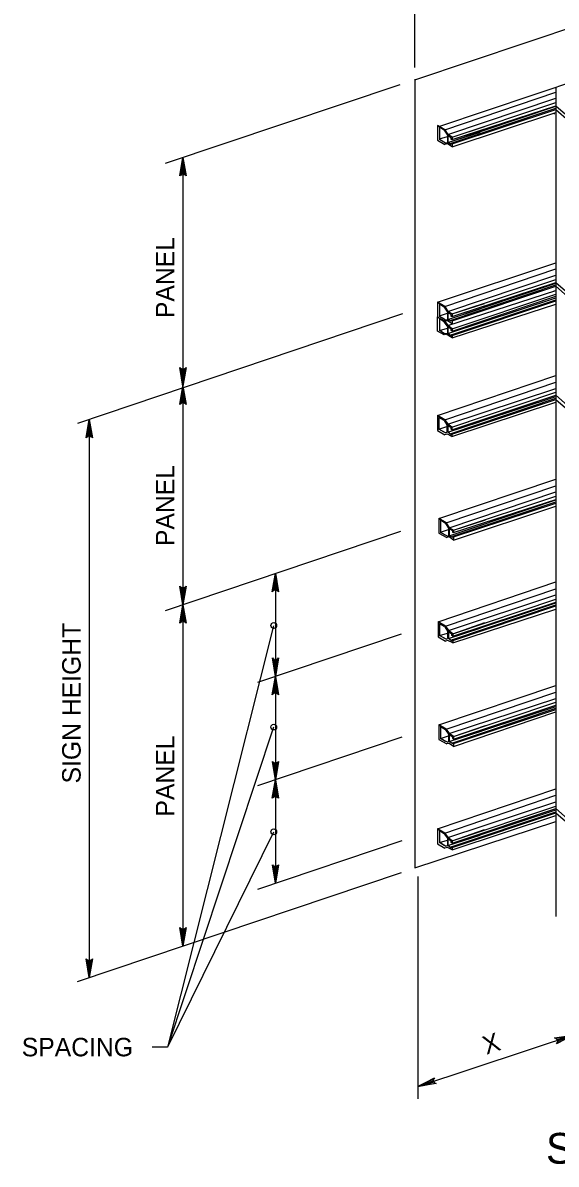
# Model space of a CAD drawing. Extents: x 650495 to 652241, y 298458 to 299646.
# Drawn here: x 650741.8 to 650828.3, y 299357.5 to 299542.7 of the extents above; entities that cross this region are included whole.
import ezdxf

# ---------------------------------------------------------------- set-up
doc = ezdxf.new("R2010")
doc.units = 0
doc.layers.add('2', color=7, linetype='Continuous')
doc.layers.add('3', color=7, linetype='Continuous')

# ---------------------------------------------------------------- blocks, each defined once
blk = doc.blocks.new('RARROW')
at = {"layer": '3'}
blk.add_lwpolyline([(-2.2695, 0.285), (-2.184875, 0.12075), (0, 0), (-2.2695, 0.285), (-2.38575, 0.384625), (0, 0), (-2.183125, -0.108), (-2.262875, -0.2705), (0, 0), (-2.38575, -0.379125), (-2.262875, -0.2705)], dxfattribs=at)

msp = doc.modelspace()

# ---------------------------------------------------------------- linework, layer by layer
at = {"layer": '2'}
for p, q in [((650805.4, 299533.47), (650908.3, 299568.07)), ((650805.4, 299535.47), (650805.4, 299567.07)), ((650809.3, 299525.87), (650904, 299557.67)), ((650803, 299532.67), (650764.9, 299519.87)), ((650805.4, 299533.57), (650805.4, 299405.57)), ((650828.3, 299532.27), (650828.3, 299397.67)), ((650810.3, 299525.37), (650828.3, 299531.47)), ((650810.8, 299524.57), (650828.3, 299530.47)), ((650810.8, 299523.27), (650828.3, 299529.17)), ((650811.3, 299523.17), (650828.3, 299528.87)), ((650811.5, 299524.17), (650828.3, 299529.77)), ((650811.5, 299523.77), (650828.3, 299529.27)), ((650811.5, 299523.07), (650828.3, 299528.67)), ((650828.3, 299529.27), (650832.8, 299525.37)), ((650828.3, 299528.67), (650832.8, 299524.67)), ((650811.5, 299522.57), (650828.3, 299528.17)), ((650828, 299527.97), (650828, 299527.87)), ((650828.3, 299528.17), (650828.3, 299528.17)), ((650809.1, 299526.07), (650809.1, 299526.07)), ((650810.3, 299525.37), (650809.1, 299526.07)), ((650809.1, 299526.07), (650809.1, 299523.67)), ((650809.1, 299526.07), (650810.3, 299525.37)), ((650809.4, 299525.77), (650809.4, 299523.77)), ((650810.2, 299525.27), (650809.4, 299525.77)), ((650810.2, 299525.27), (650810.7, 299524.47)), ((650810.3, 299525.37), (650810.8, 299524.57)), ((650810.8, 299523.27), (650816, 299524.97)), ((650811.5, 299524.17), (650816.7, 299525.87)), ((650811.5, 299523.77), (650816.7, 299525.47)), ((650809.1, 299523.67), (650810.3, 299522.97)), ((650809.4, 299523.87), (650810.7, 299524.27)), ((650810.4, 299523.17), (650809.4, 299523.77)), ((650810.2, 299523.37), (650809.4, 299523.77)), ((650810.7, 299523.07), (650810.3, 299522.97)), ((650810.4, 299523.17), (650810.7, 299523.27)), ((650810.7, 299524.57), (650810.7, 299523.27)), ((650811.5, 299522.57), (650810.7, 299523.07)), ((650811.5, 299524.17), (650810.8, 299524.57)), ((650811.3, 299524.07), (650810.8, 299524.37)), ((650811.3, 299524.07), (650810.8, 299524.37)), ((650810.8, 299524.37), (650810.8, 299523.27)), ((650811.3, 299522.97), (650810.8, 299523.27)), ((650811.3, 299524.07), (650811.3, 299523.87)), ((650811.3, 299523.77), (650811.3, 299524.07)), ((650811.5, 299523.77), (650811.3, 299523.87)), ((650811.5, 299523.77), (650811.3, 299523.77)), ((650811.3, 299523.17), (650811.3, 299522.97)), ((650811.5, 299523.07), (650811.3, 299523.17)), ((650811.3, 299523.17), (650811.3, 299522.97)), ((650811.5, 299523.07), (650811.3, 299523.17)), ((650811.5, 299524.17), (650811.5, 299523.77)), ((650811.5, 299524.17), (650811.5, 299523.77)), ((650811.5, 299523.07), (650811.5, 299522.57)), ((650811.5, 299523.07), (650811.5, 299522.57)), ((650767.8, 299520.87), (650767.8, 299512.47)), ((650767.8, 299520.87), (650767.8, 299483.77)), ((650809.1, 299497.37), (650828.3, 299503.77)), ((650810.3, 299496.67), (650828.3, 299502.77)), ((650810.8, 299495.87), (650828.3, 299501.77)), ((650811.5, 299495.47), (650828.3, 299501.07)), ((650810.8, 299494.57), (650828.3, 299500.47)), ((650810.8, 299493.57), (650828.3, 299499.27)), ((650811.3, 299494.47), (650828.3, 299500.17)), ((650811.5, 299495.07), (650828.3, 299500.57)), ((650811.5, 299494.37), (650828.3, 299499.97)), ((650828, 299499.27), (650828, 299499.17)), ((650828.3, 299500.57), (650832.8, 299496.67)), ((650828.3, 299499.97), (650832.8, 299495.97)), ((650828.3, 299499.47), (650828.3, 299499.47)), ((650810.3, 299496.67), (650809.1, 299497.37)), ((650809.1, 299497.37), (650809.1, 299494.97)), ((650809.1, 299497.37), (650810.3, 299496.67)), ((650809.4, 299497.07), (650809.4, 299495.07)), ((650810.2, 299496.57), (650809.4, 299497.07)), ((650810.8, 299492.27), (650828.3, 299498.07)), ((650811.3, 299492.07), (650828.3, 299497.77)), ((650811.5, 299493.07), (650828.3, 299498.67)), ((650811.5, 299492.67), (650828.3, 299498.37)), ((650811.5, 299491.97), (650828.3, 299497.57)), ((650811.5, 299495.47), (650816.7, 299497.17)), ((650811.5, 299491.57), (650828.3, 299497.07)), ((650803.4, 299495.47), (650750.69, 299477.67)), ((650809.4, 299495.17), (650810.7, 299495.57)), ((650810.2, 299496.57), (650810.7, 299495.77)), ((650810.3, 299496.67), (650810.8, 299495.87)), ((650810.7, 299495.87), (650810.7, 299494.57)), ((650810.8, 299494.57), (650816, 299496.27)), ((650811.5, 299495.47), (650810.8, 299495.87)), ((650811.3, 299495.37), (650810.8, 299495.67)), ((650811.3, 299495.37), (650810.8, 299495.67)), ((650810.8, 299495.67), (650810.8, 299494.57)), ((650811.3, 299495.37), (650811.3, 299495.17)), ((650811.3, 299495.07), (650811.3, 299495.37)), ((650811.5, 299495.07), (650811.3, 299495.17)), ((650811.5, 299495.07), (650816.7, 299496.77)), ((650811.5, 299495.47), (650811.5, 299495.07)), ((650811.5, 299495.47), (650811.5, 299495.07)), ((650809.1, 299492.67), (650809.1, 299494.97)), ((650809.1, 299494.97), (650810.3, 299494.27)), ((650810.4, 299494.47), (650809.4, 299495.07)), ((650810.2, 299494.67), (650809.4, 299495.07)), ((650809.4, 299494.67), (650809.4, 299492.77)), ((650810.2, 299494.17), (650809.4, 299494.67)), ((650810.7, 299493.47), (650810.2, 299494.17)), ((650810.7, 299494.37), (650810.3, 299494.27)), ((650810.3, 299494.27), (650810.8, 299493.57)), ((650810.4, 299494.47), (650810.7, 299494.57)), ((650810.5, 299493.87), (650810.5, 299493.87)), ((650811.5, 299493.87), (650810.7, 299494.37)), ((650810.7, 299493.47), (650810.7, 299492.37)), ((650811.3, 299494.27), (650810.8, 299494.57)), ((650811.5, 299493.07), (650810.8, 299493.57)), ((650811.3, 299492.97), (650810.8, 299493.37)), ((650810.8, 299493.37), (650810.8, 299492.27)), ((650811.5, 299495.07), (650811.3, 299495.07)), ((650811.3, 299494.47), (650811.3, 299494.27)), ((650811.5, 299494.37), (650811.3, 299494.47)), ((650811.3, 299494.47), (650811.3, 299494.27)), ((650811.5, 299494.37), (650811.3, 299494.47)), ((650811.5, 299494.37), (650811.5, 299493.87)), ((650811.5, 299494.37), (650811.5, 299493.87)), ((650810.2, 299492.07), (650809.1, 299492.67)), ((650809.4, 299492.77), (650810.7, 299493.17)), ((650810.2, 299492.27), (650809.4, 299492.77)), ((650810.2, 299492.27), (650810.7, 299492.37)), ((650810.5, 299492.17), (650810.2, 299492.07)), ((650811.5, 299491.57), (650810.5, 299492.17)), ((650811.3, 299491.87), (650810.8, 299492.27)), ((650811.3, 299492.77), (650811.3, 299492.97)), ((650811.5, 299492.67), (650811.3, 299492.77)), ((650811.3, 299492.07), (650811.3, 299491.87)), ((650811.5, 299491.97), (650811.3, 299492.07)), ((650811.5, 299493.07), (650811.5, 299492.67)), ((650811.5, 299491.97), (650811.5, 299491.57)), ((650809.1, 299478.97), (650828.3, 299485.47)), ((650810.3, 299478.27), (650828.3, 299484.37)), ((650767.8, 299483.77), (650767.8, 299437.57)), ((650810.8, 299477.57), (650828.3, 299483.37)), ((650811.4, 299477.07), (650828.3, 299482.77)), ((650811.4, 299476.67), (650828.3, 299482.27)), ((650828.3, 299482.27), (650832.8, 299478.27)), ((650810.8, 299476.27), (650828.3, 299482.07)), ((650811.3, 299476.07), (650828.3, 299481.77)), ((650811.4, 299475.97), (650828.3, 299481.57)), ((650811.4, 299475.57), (650828.3, 299481.17)), ((650828.3, 299481.57), (650832.8, 299477.67)), ((650809.1, 299478.97), (650809.1, 299478.97)), ((650810.3, 299478.27), (650809.1, 299478.97)), ((650809.1, 299478.97), (650809.1, 299476.57)), ((650809.1, 299478.97), (650810.3, 299478.27)), ((650809.3, 299478.67), (650809.3, 299476.77)), ((650810.2, 299478.17), (650809.3, 299478.67)), ((650811.4, 299477.07), (650816.7, 299478.87)), ((650752.6, 299478.31), (650752.6, 299387.77)), ((650809.1, 299476.57), (650810.3, 299475.87)), ((650809.3, 299476.77), (650810.6, 299477.17)), ((650810.4, 299476.17), (650809.3, 299476.77)), ((650810.2, 299476.27), (650809.3, 299476.77)), ((650810.2, 299478.17), (650810.6, 299477.47)), ((650810.3, 299478.27), (650810.8, 299477.57)), ((650810.6, 299477.47), (650810.6, 299476.27)), ((650810.8, 299476.27), (650815.9, 299477.97)), ((650811.4, 299477.07), (650810.8, 299477.57)), ((650811.3, 299476.97), (650810.8, 299477.37)), ((650811.3, 299476.97), (650810.8, 299477.37)), ((650810.8, 299477.37), (650810.8, 299476.27)), ((650811.3, 299476.97), (650811.3, 299476.77)), ((650811.3, 299476.77), (650811.3, 299476.97)), ((650811.4, 299476.67), (650811.3, 299476.77)), ((650811.4, 299476.67), (650811.3, 299476.77)), ((650811.4, 299476.67), (650816.7, 299478.37)), ((650811.4, 299477.07), (650811.4, 299476.67)), ((650811.4, 299477.07), (650811.4, 299476.67)), ((650810.7, 299475.97), (650810.3, 299475.87)), ((650810.4, 299476.17), (650810.6, 299476.27)), ((650811.4, 299475.57), (650810.7, 299475.97)), ((650811.3, 299475.87), (650810.8, 299476.27)), ((650811.3, 299476.07), (650811.3, 299475.87)), ((650811.4, 299475.97), (650811.3, 299476.07)), ((650811.3, 299476.07), (650811.3, 299475.87)), ((650811.4, 299475.97), (650811.3, 299476.07)), ((650811.4, 299475.97), (650811.4, 299475.57)), ((650811.4, 299475.97), (650811.4, 299475.57)), ((650809.3, 299462.27), (650828.3, 299468.67)), ((650810.5, 299461.57), (650828.3, 299467.57)), ((650811, 299460.77), (650828.3, 299466.57)), ((650811.7, 299460.37), (650828.3, 299465.87)), ((650811, 299459.47), (650828.3, 299465.27)), ((650811.6, 299459.37), (650828.3, 299464.97)), ((650811.7, 299459.97), (650828.3, 299465.37)), ((650811.7, 299459.27), (650828.3, 299464.77)), ((650811.7, 299458.77), (650828.3, 299464.27)), ((650809.3, 299462.27), (650809.3, 299462.27)), ((650810.5, 299461.57), (650809.3, 299462.27)), ((650809.3, 299462.27), (650809.3, 299459.87)), ((650809.3, 299462.27), (650810.5, 299461.57)), ((650809.6, 299461.97), (650809.6, 299459.97)), ((650810.4, 299461.47), (650809.6, 299461.97)), ((650811.7, 299460.37), (650816.9, 299462.07)), ((650803.1, 299460.17), (650764.9, 299447.27)), ((650809.6, 299460.07), (650810.9, 299460.47)), ((650810.7, 299459.37), (650809.6, 299459.97)), ((650810.4, 299459.57), (650809.6, 299459.97)), ((650810.4, 299461.47), (650810.9, 299460.67)), ((650810.5, 299461.57), (650811, 299460.77)), ((650810.9, 299460.77), (650810.9, 299459.47)), ((650811, 299459.47), (650816.2, 299461.17)), ((650811.7, 299460.37), (650811, 299460.77)), ((650811.6, 299460.27), (650811, 299460.57)), ((650811.6, 299460.27), (650811, 299460.57)), ((650811, 299460.57), (650811, 299459.47)), ((650811.6, 299460.27), (650811.6, 299460.07)), ((650811.6, 299459.97), (650811.6, 299460.27)), ((650811.7, 299459.97), (650811.6, 299460.07)), ((650811.7, 299459.97), (650811.6, 299459.97)), ((650811.7, 299459.97), (650816.9, 299461.67)), ((650811.7, 299460.37), (650811.7, 299459.97)), ((650811.7, 299460.37), (650811.7, 299459.97)), ((650809.3, 299459.87), (650810.6, 299459.17)), ((650811, 299459.27), (650810.6, 299459.17)), ((650810.7, 299459.37), (650810.9, 299459.47)), ((650811.6, 299459.17), (650811, 299459.47)), ((650811.7, 299458.77), (650811, 299459.27)), ((650811.6, 299459.37), (650811.6, 299459.17)), ((650811.7, 299459.27), (650811.6, 299459.37)), ((650811.6, 299459.37), (650811.6, 299459.17)), ((650811.7, 299459.27), (650811.6, 299459.37)), ((650811.7, 299459.27), (650811.7, 299458.77)), ((650811.7, 299459.27), (650811.7, 299458.77)), ((650782.8, 299453.31), (650782.8, 299403.07)), ((650809.2, 299445.47), (650828.3, 299451.97)), ((650810.4, 299444.77), (650828.3, 299450.87)), ((650810.9, 299444.07), (650828.3, 299449.87)), ((650811.6, 299443.57), (650828.3, 299449.17)), ((650767.8, 299448.27), (650767.8, 299392.87)), ((650810.9, 299442.77), (650828.3, 299448.57)), ((650811.4, 299442.57), (650828.3, 299448.27)), ((650811.6, 299443.17), (650828.3, 299448.67)), ((650811.6, 299442.47), (650828.3, 299448.07)), ((650811.6, 299442.07), (650828.3, 299447.57)), ((650809.2, 299445.47), (650809.2, 299445.47)), ((650810.4, 299444.77), (650809.2, 299445.47)), ((650809.2, 299445.47), (650809.2, 299443.07)), ((650809.2, 299445.47), (650810.4, 299444.77)), ((650809.4, 299445.17), (650809.4, 299443.27)), ((650810.3, 299444.67), (650809.4, 299445.17)), ((650811.6, 299443.57), (650816.8, 299445.37)), ((650782.5, 299444.87), (650765.3, 299376.47)), ((650803.2, 299443.47), (650779.9, 299435.67)), ((650809.4, 299443.27), (650810.7, 299443.67)), ((650810.5, 299442.67), (650809.4, 299443.27)), ((650810.3, 299442.77), (650809.4, 299443.27)), ((650810.3, 299444.67), (650810.7, 299443.97)), ((650810.4, 299444.77), (650810.9, 299444.07)), ((650810.7, 299443.97), (650810.7, 299442.77)), ((650810.9, 299442.77), (650816, 299444.47)), ((650811.6, 299443.57), (650810.9, 299444.07)), ((650811.4, 299443.47), (650810.9, 299443.87)), ((650811.4, 299443.47), (650810.9, 299443.87)), ((650810.9, 299443.87), (650810.9, 299442.77)), ((650811.4, 299443.47), (650811.4, 299443.27)), ((650811.4, 299443.27), (650811.4, 299443.47)), ((650811.6, 299443.17), (650811.4, 299443.27)), ((650811.6, 299443.17), (650811.4, 299443.27)), ((650811.6, 299443.17), (650816.8, 299444.87)), ((650811.6, 299443.57), (650811.6, 299443.17)), ((650811.6, 299443.57), (650811.6, 299443.17)), ((650809.2, 299443.07), (650810.4, 299442.37)), ((650810.8, 299442.47), (650810.4, 299442.37)), ((650810.5, 299442.67), (650810.7, 299442.77)), ((650811.6, 299442.07), (650810.8, 299442.47)), ((650811.4, 299442.37), (650810.9, 299442.77)), ((650811.4, 299442.57), (650811.4, 299442.37)), ((650811.6, 299442.47), (650811.4, 299442.57)), ((650811.4, 299442.57), (650811.4, 299442.37)), ((650811.6, 299442.47), (650811.4, 299442.57)), ((650811.6, 299442.47), (650811.6, 299442.07)), ((650811.6, 299442.47), (650811.6, 299442.07)), ((650809.3, 299428.77), (650828.3, 299435.17)), ((650810.5, 299428.07), (650828.3, 299434.07)), ((650811, 299427.37), (650828.3, 299433.07)), ((650811.7, 299426.87), (650828.3, 299432.47)), ((650811, 299426.07), (650828.3, 299431.77)), ((650811.6, 299425.87), (650828.3, 299431.47)), ((650811.7, 299426.47), (650828.3, 299431.97)), ((650811.7, 299425.77), (650828.3, 299431.27)), ((650811.7, 299425.27), (650828.3, 299430.87)), ((650809.3, 299428.77), (650809.3, 299428.77)), ((650810.5, 299428.07), (650809.3, 299428.77)), ((650809.3, 299428.77), (650809.3, 299426.37)), ((650809.3, 299428.77), (650810.5, 299428.07)), ((650809.6, 299428.47), (650809.6, 299426.57)), ((650810.4, 299427.97), (650809.6, 299428.47)), ((650811.7, 299426.87), (650816.9, 299428.67)), ((650782.5, 299428.37), (650765.3, 299376.47)), ((650803.3, 299426.77), (650779.9, 299418.87)), ((650809.6, 299426.57), (650810.9, 299426.97)), ((650810.7, 299425.97), (650809.6, 299426.57)), ((650810.4, 299426.07), (650809.6, 299426.57)), ((650810.4, 299427.97), (650810.9, 299427.27)), ((650810.5, 299428.07), (650811, 299427.37)), ((650810.9, 299427.27), (650810.9, 299426.07)), ((650811, 299426.07), (650816.2, 299427.77)), ((650811.7, 299426.87), (650811, 299427.37)), ((650811.6, 299426.77), (650811, 299427.17)), ((650811.6, 299426.77), (650811, 299427.17)), ((650811, 299427.17), (650811, 299426.07)), ((650811.6, 299426.77), (650811.6, 299426.57)), ((650811.6, 299426.57), (650811.6, 299426.77)), ((650811.7, 299426.47), (650811.6, 299426.57)), ((650811.7, 299426.47), (650811.6, 299426.57)), ((650811.7, 299426.47), (650816.9, 299428.17)), ((650811.7, 299426.87), (650811.7, 299426.47)), ((650811.7, 299426.87), (650811.7, 299426.47)), ((650809.3, 299426.37), (650810.6, 299425.67)), ((650811, 299425.77), (650810.6, 299425.67)), ((650810.7, 299425.97), (650810.9, 299426.07)), ((650811.6, 299425.67), (650811, 299426.07)), ((650811.7, 299425.27), (650811, 299425.77)), ((650811.6, 299425.87), (650811.6, 299425.67)), ((650811.7, 299425.77), (650811.6, 299425.87)), ((650811.6, 299425.87), (650811.6, 299425.67)), ((650811.7, 299425.77), (650811.6, 299425.87)), ((650811.7, 299425.77), (650811.7, 299425.27)), ((650811.7, 299425.77), (650811.7, 299425.27)), ((650805.9, 299370.07), (650949.3, 299417.67)), ((650809.1, 299411.87), (650828.3, 299418.37)), ((650810.3, 299411.17), (650828.3, 299417.37)), ((650810.8, 299410.47), (650828.3, 299416.27)), ((650811.5, 299409.97), (650828.3, 299415.57)), ((650810.8, 299409.17), (650828.3, 299414.97)), ((650811.3, 299408.97), (650828.3, 299414.67)), ((650811.5, 299409.57), (650828.3, 299415.17)), ((650811.5, 299408.87), (650828.3, 299414.47)), ((650811.5, 299408.47), (650828.3, 299414.07)), ((650828.3, 299415.17), (650832.8, 299411.17)), ((650828.3, 299414.47), (650832.8, 299410.57)), ((650805.4, 299405.57), (650828.3, 299413.07)), ((650809.1, 299411.87), (650809.1, 299411.87)), ((650810.3, 299411.17), (650809.1, 299411.87)), ((650809.1, 299411.87), (650809.1, 299409.47)), ((650809.1, 299411.87), (650810.3, 299411.17)), ((650811.5, 299409.97), (650816.7, 299411.77)), ((650782.5, 299411.37), (650765.3, 299376.47)), ((650803.3, 299409.97), (650779.9, 299402.07)), ((650809.4, 299411.57), (650809.4, 299409.67)), ((650810.2, 299411.07), (650809.4, 299411.57)), ((650809.4, 299409.67), (650810.7, 299410.07)), ((650810.2, 299411.07), (650810.7, 299410.37)), ((650810.3, 299411.17), (650810.8, 299410.47)), ((650810.7, 299410.37), (650810.7, 299409.17)), ((650810.8, 299409.17), (650816, 299410.87)), ((650811.5, 299409.97), (650810.8, 299410.47)), ((650811.3, 299409.87), (650810.8, 299410.27)), ((650811.3, 299409.87), (650810.8, 299410.27)), ((650810.8, 299410.27), (650810.8, 299409.17)), ((650811.3, 299409.87), (650811.3, 299409.67)), ((650811.3, 299409.67), (650811.3, 299409.87)), ((650811.5, 299409.57), (650816.7, 299411.27)), ((650811.5, 299409.97), (650811.5, 299409.57)), ((650811.5, 299409.97), (650811.5, 299409.57)), ((650809.1, 299409.47), (650810.3, 299408.77)), ((650810.4, 299409.07), (650809.4, 299409.67)), ((650810.2, 299409.17), (650809.4, 299409.67)), ((650810.7, 299408.87), (650810.3, 299408.77)), ((650810.4, 299409.07), (650810.7, 299409.17)), ((650811.5, 299408.47), (650810.7, 299408.87)), ((650811.3, 299408.77), (650810.8, 299409.17)), ((650811.5, 299409.57), (650811.3, 299409.67)), ((650811.5, 299409.57), (650811.3, 299409.67)), ((650811.3, 299408.97), (650811.3, 299408.77)), ((650811.5, 299408.87), (650811.3, 299408.97)), ((650811.3, 299408.97), (650811.3, 299408.77)), ((650811.5, 299408.87), (650811.3, 299408.97)), ((650811.5, 299408.87), (650811.5, 299408.47)), ((650811.5, 299408.87), (650811.5, 299408.47)), ((650803.2, 299404.77), (650750.66, 299387.07)), ((650805.9, 299404.17), (650805.9, 299368.07)), ((650765.3, 299376.47), (650762.8, 299376.47)), ((650765.3, 299376.47), (650762.8, 299376.47)), ((650765.3, 299376.47), (650762.8, 299376.47))]:
    msp.add_line(p, q, dxfattribs=at)
for centre in [(650782.53, 299444.9), (650782.53, 299428.41), (650782.53, 299411.41)]:
    msp.add_circle(centre, 0.467, dxfattribs=at)

# ---------------------------------------------------------------- block references
for p, xscale, yscale, rotation in [((650767.8, 299520.87), 1.2574347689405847, 1.3092961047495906, 89.99999999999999), ((650767.8, 299483.77), 1.2574347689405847, 1.3092961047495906, -90.00000000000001), ((650767.8, 299483.77), 1.2574347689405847, 1.3092961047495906, 89.99999999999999), ((650752.6, 299478.34), 1.2574347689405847, 1.3092961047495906, 89.99999999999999), ((650782.8, 299453.37), 1.2574347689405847, 1.3092961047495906, 89.99999999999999), ((650767.8, 299448.27), 1.2574347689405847, 1.3092961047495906, -90.00000000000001), ((650767.8, 299448.27), 1.2574347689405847, 1.3092961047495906, 89.99999999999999), ((650782.8, 299436.64), 1.2574347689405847, 1.3092961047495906, -90.00000000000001), ((650782.8, 299436.64), 1.2574347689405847, 1.3092961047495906, 89.99999999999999), ((650782.8, 299419.85), 1.2574347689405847, 1.3092961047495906, -90.00000000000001), ((650782.8, 299419.85), 1.2574347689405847, 1.3092961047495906, 89.99999999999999), ((650782.8, 299403.07), 1.2574347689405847, 1.3092961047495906, -90.00000000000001), ((650767.8, 299392.87), 1.2574347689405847, 1.3092961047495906, -90.00000000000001), ((650752.6, 299387.77), 1.2574347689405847, 1.3092961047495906, -90.00000000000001), ((650831.1, 299378.43), 1.2574347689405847, 1.3092961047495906, 18.62052730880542), ((650805.9, 299370.07), 1.2574347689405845, 1.3092961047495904, -161.56373355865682)]:
    msp.add_blockref('RARROW', p, dxfattribs=dict(at, xscale=xscale, yscale=yscale, rotation=rotation))

# ---------------------------------------------------------------- texts
for s, rotation, p in [('PANEL', 90, (650766.4, 299494.79)), ('PANEL', 90, (650766.4, 299457.79)), ('SIGN HEIGHT', 90, (650751.2, 299419.26)), ('PANEL', 90, (650766.4, 299413.89)), ('X', 18.3451, (650817.02, 299375.21))]:
    msp.add_text(s, height=3, rotation=rotation, dxfattribs=at).set_placement(p)
for s, height, p in [('SPACING', 3, (650741.64, 299374.97)), ('STIFFENER LOCATION', 5, (650826.7, 299357.54))]:
    msp.add_text(s, height=height, dxfattribs=at).set_placement(p)

doc.saveas('drawing.dxf')
